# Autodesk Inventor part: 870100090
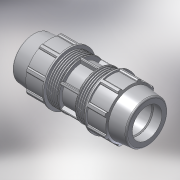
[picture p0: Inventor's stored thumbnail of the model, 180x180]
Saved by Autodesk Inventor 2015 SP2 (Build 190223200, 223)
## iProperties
Created: 2017-02
Part Number: 870100090
Material: PVC-Piping
Description: PLASSON REPAIR COUPLER 90
Document SubType Name: Modeling
Designer: KIM
Mass: 2387.75 g
Surface Area: 2478.17 cm^2
Volume: 1705.54 cm^3
Density: 1.4 g/cm^3
Appearance: Smooth - White
Author: KIM
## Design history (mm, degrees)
derived "87610.ipt"
feature "Solid1::87610.ipt"
tag "TaggingFeature1"
body "Solid1"
other parameters: "d1" = 334, "d4" = 27.83333, "d5" = 47.71429, "d7" = 152, "d8" = 114, "d9" = 47.71429, "d11" = 4.77143, "d12" = 121.6, "d13" = 120 deg, "d14" = 117, "d15" = 6 deg, "d16" = 136.8, "d18" = 4.5, "d19" = 35 deg, "d20" = 17.5 deg, "d21" = 141.36, "d23" = 0, "d25" = 360 deg, "d27" = 3.04, "d33" = 1.8, "d34" = 7.6, "d36" = 0, "d37" = 1.8, "d38" = 1.8, "d40" = 360 deg, "d42" = 60.12, "d46" = 2.7, "d50" = 4.175, "d51" = 0, "d53" = 3.05371, "d54" = 3.05371, "d57" = 6.10743, "d62" = 134.064, "E_" = 152, "H_" = 334, "l_" = 143, "d52" = 30.53714
